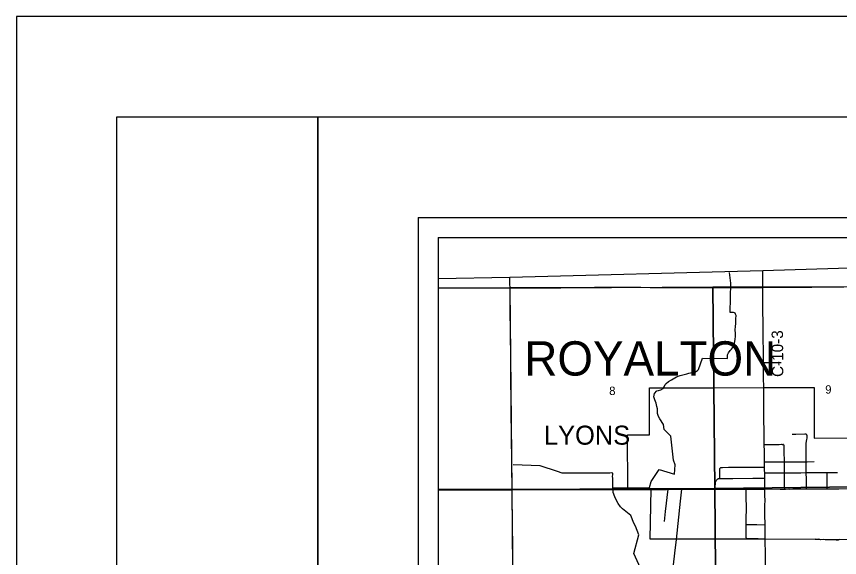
# Model space of a CAD drawing. Extents: x 0 to 34, y 0 to 22.
# Drawn here: x 0 to 4.098, y 19.309 to 22 of the extents above; entities that cross this region are included whole.
import ezdxf

# ---------------------------------------------------------------- set-up
doc = ezdxf.new("R2010")
doc.units = 0
for name, color, linetype in [('Default', 7, 'Continuous'), ('GM_X_City_Street', 7, 'Continuous'), ('GM_X_Corporation', 7, 'Continuous'), ('GM_X_Corporation_Text', 7, 'Continuous'), ('GM_X_County_Road', 7, 'Continuous'), ('GM_X_County_Road_Text', 7, 'Continuous'), ('GM_X_Minor_River', 7, 'Continuous'), ('GM_X_Rail_Line', 7, 'Continuous'), ('GM_X_Section', 7, 'Continuous'), ('GM_X_Section_Text', 7, 'Continuous'), ('GM_X_State_Route', 7, 'Continuous'), ('GM_X_Township_Road', 7, 'Continuous'), ('GM_X_Township_Text', 7, 'Continuous'), ('SH_Border', 7, 'Continuous'), ('SH_Cut_Line', 7, 'Continuous'), ('SH_Data', 7, 'Continuous')]:
    doc.layers.add(name, color=color, linetype=linetype)

msp = doc.modelspace()

# ---------------------------------------------------------------- linework, layer by layer
at = {"layer": 'Default'}
msp.add_lwpolyline([(4.4698, 20.7584), (3.7151, 20.7343), (2.4566, 20.7022), (2.1, 20.6957), (2.1, 16.6348)], dxfattribs=at)
for points in [[(2.1, 20.648), (2.1, 19.6466), (2.4678, 19.6478), (2.4571, 20.6489)], [(2.1, 19.6466), (2.1, 18.6532), (2.4755, 18.6539), (2.4678, 19.6478)]]:
    msp.add_lwpolyline(points, close=True, dxfattribs=at)
at = {"layer": 'GM_X_City_Street'}
for points in [[(3.9318, 19.8282), (3.9317, 19.8653), (3.9316, 19.8725), (3.9316, 19.8756), (3.9319, 19.8806), (3.9323, 19.8841), (3.9336, 19.8901), (3.9345, 19.8944), (3.935, 19.8964), (3.9361, 19.9031), (3.9364, 19.9051), (3.9367, 19.907), (3.9368, 19.9096), (3.9368, 19.9116), (3.9367, 19.9136), (3.9361, 19.9161), (3.9354, 19.9182), (3.9342, 19.9198), (3.9335, 19.9206), (3.9328, 19.9212), (3.9321, 19.9215), (3.9312, 19.9219), (3.9299, 19.9222), (3.9281, 19.9225), (3.9251, 19.9225), (3.8793, 19.9215), (3.8612, 19.9209)], [(3.7229, 19.8714), (3.7584, 19.8713), (3.7963, 19.8717), (3.8089, 19.8719), (3.812, 19.8718), (3.8152, 19.8714)], [(3.8246, 19.6496), (3.8243, 19.6651), (3.8239, 19.6776), (3.8237, 19.7026), (3.8234, 19.7301), (3.8229, 19.785), (3.8223, 19.8379), (3.8223, 19.864), (3.8222, 19.865), (3.8222, 19.8657), (3.8216, 19.867), (3.8207, 19.868), (3.8194, 19.8692), (3.8186, 19.8699), (3.8178, 19.8704), (3.817, 19.8709), (3.8163, 19.8711), (3.8152, 19.8714)], [(3.9331, 19.6501), (3.9324, 19.6643), (3.9326, 19.6969), (3.9322, 19.7311), (3.9321, 19.7439), (3.9319, 19.7731), (3.9316, 19.7853), (3.9318, 19.8282)], [(3.5014, 19.7018), (3.5014, 19.7174), (3.5015, 19.7331), (3.5014, 19.7456), (3.5015, 19.7472), (3.5017, 19.7487), (3.502, 19.7501), (3.5024, 19.7515), (3.5029, 19.7527), (3.5038, 19.754), (3.5046, 19.755), (3.5061, 19.7561)], [(3.5061, 19.7561), (3.5079, 19.7567), (3.5094, 19.757), (3.5112, 19.757), (3.5143, 19.7572), (3.5451, 19.7575), (3.659, 19.7578), (3.7084, 19.758), (3.7243, 19.758)], [(3.7239, 19.7848), (3.7673, 19.7848), (3.8229, 19.785), (3.825, 19.785), (3.8797, 19.7852), (3.9316, 19.7853), (3.9362, 19.7852), (3.9716, 19.7863)], [(3.7249, 19.7306), (3.744, 19.7303), (3.7497, 19.73), (3.7618, 19.7303), (3.8234, 19.7301), (3.861, 19.7299), (3.9046, 19.7303), (3.9322, 19.7311), (3.954, 19.7314), (3.9913, 19.7319), (4.0131, 19.7321), (4.0355, 19.7322), (4.0691, 19.7322), (4.0878, 19.7325)], [(4.0366, 19.6505), (4.0362, 19.6729), (4.0358, 19.7009), (4.0355, 19.7322)], [(3.4796, 19.6491), (3.4789, 19.6605), (3.4798, 19.6776), (3.4803, 19.6824), (3.4808, 19.6839), (3.4819, 19.6876), (3.4837, 19.6913), (3.4854, 19.6938), (3.4876, 19.6963), (3.4896, 19.6984), (3.4912, 19.6997), (3.4928, 19.7006), (3.4943, 19.7011), (3.4977, 19.7016), (3.5014, 19.7018)], [(3.5014, 19.7018), (3.5215, 19.7021), (3.5551, 19.7023), (3.567, 19.7026), (3.6655, 19.703), (3.7118, 19.7032), (3.7256, 19.7032)], [(3.2268, 19.488), (3.2318, 19.5371), (3.244, 19.6495)], [(3.634, 19.4055), (3.6336, 19.4064), (3.6334, 19.4074), (3.6333, 19.4082), (3.6333, 19.4088), (3.6331, 19.413), (3.6329, 19.422), (3.6327, 19.4441), (3.6324, 19.4689), (3.6325, 19.4725), (3.6324, 19.4936), (3.6337, 19.5617), (3.6334, 19.605), (3.6328, 19.6494)], [(3.6325, 19.4725), (3.6444, 19.4728), (3.6539, 19.4725), (3.6852, 19.4726), (3.727, 19.4721)], [(3.634, 19.4055), (3.6344, 19.4049), (3.635, 19.4045), (3.6358, 19.404), (3.6367, 19.4036), (3.6377, 19.4033), (3.6388, 19.4031), (3.6407, 19.403), (3.6431, 19.4029), (3.6556, 19.4027), (3.6932, 19.4028), (3.7183, 19.4024), (3.7276, 19.4023)]]:
    msp.add_lwpolyline(points, dxfattribs=at)
at = {"layer": 'GM_X_Corporation'}
msp.add_lwpolyline([(3.155, 19.3995), (3.1598, 19.65), (3.0434, 19.6498), (3.0413, 19.9196), (3.1522, 19.9187), (3.151, 20.1523), (3.4671, 20.153), (3.72, 20.1538), (3.9709, 20.1548), (3.9717, 19.9024), (4.2217, 19.9047), (4.2244, 19.6529), (4.2237, 19.397), (3.7274, 19.3997), (3.2857, 19.3997)], close=True, dxfattribs=at)
at = {"layer": 'GM_X_County_Road'}
for p, q in [((3.7243, 19.758), (3.7239, 19.7848)), ((3.7256, 19.7032), (3.7249, 19.7306)), ((3.7258, 19.6283), (3.7258, 19.6501)), ((3.7276, 19.4023), (3.727, 19.4721))]:
    msp.add_line(p, q, dxfattribs=at)
for points in [[(3.7161, 20.6524), (3.716, 20.6583), (3.7157, 20.7081), (3.7153, 20.7337)], [(2.4571, 20.6512), (2.457, 20.6688), (2.4568, 20.7016)], [(3.7192, 20.2789), (3.7191, 20.297), (3.7186, 20.3437), (3.7179, 20.3904), (3.7165, 20.624), (3.7161, 20.6524)], [(2.4675, 19.6482), (2.467, 19.6958), (2.4669, 19.7145), (2.4665, 19.7549), (2.4643, 19.9414), (2.4632, 20.0097), (2.4627, 20.0781), (2.4613, 20.2055), (2.4606, 20.2459), (2.4606, 20.2739), (2.4587, 20.4542), (2.4582, 20.5164), (2.4576, 20.5879), (2.4571, 20.6512)], [(3.7202, 20.1532), (3.7196, 20.2053), (3.7192, 20.2789)], [(3.7229, 19.8714), (3.7209, 20.0624), (3.7204, 20.1058), (3.7202, 20.1532)], [(3.7239, 19.7848), (3.7238, 19.7993), (3.7233, 19.8366), (3.7229, 19.8714)], [(3.7249, 19.7306), (3.7244, 19.7413), (3.7244, 19.7501), (3.7243, 19.758)], [(3.7258, 19.6501), (3.7259, 19.6669), (3.7256, 19.6916), (3.7256, 19.7032)], [(2.4799, 18.3001), (2.4798, 18.3093), (2.4781, 18.4678), (2.4758, 18.6792), (2.4742, 18.8657), (2.4737, 18.9435), (2.4734, 18.9652), (2.4731, 18.9994), (2.4722, 19.0771), (2.4716, 19.1517), (2.4708, 19.2792), (2.4703, 19.3538), (2.4679, 19.6057), (2.4675, 19.6482)], [(3.7262, 19.5673), (3.7263, 19.5766), (3.7265, 19.5858), (3.7258, 19.6233), (3.7258, 19.6283)], [(3.727, 19.4721), (3.7264, 19.5235), (3.7261, 19.5641), (3.7262, 19.5673)], [(3.7277, 19.3981), (3.7277, 19.3991), (3.7276, 19.4023)], [(3.735, 18.6489), (3.7343, 18.6815), (3.7335, 18.7902), (3.7331, 18.8181), (3.7327, 18.8647), (3.7322, 18.9113), (3.7306, 19.0916), (3.73, 19.1751), (3.7291, 19.2526), (3.7285, 19.3334), (3.728, 19.3863), (3.7277, 19.3981)]]:
    msp.add_lwpolyline(points, dxfattribs=at)
at = {"layer": 'GM_X_Minor_River'}
for points in [[(2.9689, 19.656), (3.1517, 19.6572), (3.16, 19.6867), (3.2001, 19.7459), (3.2756, 19.7235), (3.2796, 19.7702), (3.2711, 19.7923), (3.2569, 19.9131), (3.2246, 19.9456), (3.2211, 19.9707), (3.2025, 19.9994), (3.1961, 20.0097), (3.1906, 20.0257), (3.1911, 20.0336), (3.1916, 20.042), (3.1912, 20.048), (3.1887, 20.0598), (3.1851, 20.0766), (3.1777, 20.0926), (3.173, 20.1074), (3.1758, 20.1245), (3.1885, 20.1384), (3.1957, 20.1402), (3.2071, 20.1427), (3.2193, 20.1491), (3.2243, 20.1574), (3.2301, 20.1695), (3.2351, 20.1747), (3.2462, 20.1841), (3.2615, 20.1923), (3.2859, 20.2072), (3.3049, 20.2139), (3.3373, 20.2227), (3.3479, 20.2252), (3.3646, 20.2288), (3.3798, 20.2329), (3.3898, 20.2392), (3.3951, 20.2449), (3.4155, 20.3004), (3.5402, 20.2996), (3.5396, 20.3171), (3.5451, 20.3276), (3.5531, 20.3378), (3.56, 20.3457), (3.5689, 20.3581), (3.5751, 20.3729), (3.5784, 20.3948), (3.5797, 20.4081), (3.5791, 20.4229), (3.5785, 20.4408), (3.5795, 20.4574), (3.5812, 20.4722), (3.5821, 20.4863), (3.5818, 20.4969), (3.5824, 20.5132), (3.5802, 20.5193), (3.5772, 20.5246), (3.5742, 20.5262), (3.5689, 20.5281), (3.5537, 20.5279), (3.5557, 20.6732), (3.5495, 20.7261)], [(3.1227, 19.2188), (3.0735, 19.329), (3.0983, 19.4209), (3.0817, 19.4647), (3.0739, 19.48), (3.0588, 19.5181), (3.0171, 19.5511), (3.007, 19.5615), (2.995, 19.5779), (2.9876, 19.592), (2.9787, 19.6115), (2.9713, 19.6324), (2.9689, 19.6545), (2.9691, 19.7011), (2.9677, 19.714), (2.9685, 19.7209), (2.9682, 19.7277), (2.9644, 19.7304), (2.9538, 19.729), (2.7169, 19.729), (2.6931, 19.7372), (2.6077, 19.7647), (2.4728, 19.7694)], [(4.0997, 19.399), (4.0902, 19.3956), (4.0804, 19.3957), (4.069, 19.3962), (4.0576, 19.3967), (4.0474, 19.3976), (4.0371, 19.3965), (4.0258, 19.3963), (4.0159, 19.3979), (4.0045, 19.3968), (3.994, 19.3996), (3.983, 19.399), (3.9758, 19.4009)]]:
    msp.add_lwpolyline(points, dxfattribs=at)
at = {"layer": 'GM_X_Rail_Line'}
msp.add_lwpolyline([(2.1, 19.6449), (2.4687, 19.6463), (3.2362, 19.6474), (3.7244, 19.6491), (5.0197, 19.6574), (5.4852, 19.6574), (5.5146, 19.6675), (5.5588, 19.7034), (6.1514, 20.0969), (6.291, 20.193), (6.3333, 20.2132), (6.3747, 20.2169), (6.4833, 20.2279), (7.4795, 20.3149), (8.1518, 20.3773), (8.7379, 20.4271), (8.9, 20.4441)], dxfattribs=at)
at = {"layer": 'GM_X_Section'}
for points in [[(2.4571, 20.6489), (3.4668, 20.6546), (3.4763, 19.6515), (2.4678, 19.6478)], [(3.4668, 20.6546), (4.4712, 20.6576), (4.4763, 19.663), (3.4763, 19.6515)], [(2.4678, 19.6478), (3.4763, 19.6515), (3.4848, 18.6515), (2.4755, 18.6539)], [(3.4763, 19.6515), (4.4763, 19.663), (4.4846, 18.6535), (3.4848, 18.6515)]]:
    msp.add_lwpolyline(points, close=True, dxfattribs=at)
at = {"layer": 'GM_X_State_Route'}
for points in [[(2.1, 19.6467), (2.1864, 19.647), (2.2953, 19.6478), (2.401, 19.6481), (2.4524, 19.6482)], [(2.4524, 19.6482), (2.4675, 19.6482), (2.5099, 19.6483), (2.569, 19.6485), (2.6312, 19.6486), (2.7338, 19.6489), (2.7867, 19.649), (2.9049, 19.649), (2.9391, 19.6491), (2.992, 19.6493), (3.0426, 19.6492)], [(3.0426, 19.6492), (3.0436, 19.6492), (3.1039, 19.6492), (3.16, 19.6494)], [(3.16, 19.6494), (3.244, 19.6495), (3.2777, 19.6495), (3.3123, 19.6496), (3.3243, 19.6496), (3.4197, 19.6492), (3.4796, 19.6491), (3.5127, 19.6492), (3.581, 19.6493), (3.5989, 19.6494)], [(3.5989, 19.6494), (3.6328, 19.6494), (3.6679, 19.6494), (3.6689, 19.6494)], [(3.6689, 19.6494), (3.7258, 19.6501), (3.7586, 19.6498)], [(3.7586, 19.6498), (3.8013, 19.6495), (3.8246, 19.6496), (3.8287, 19.6496)], [(3.8287, 19.6496), (3.8448, 19.6497), (3.848, 19.6495), (3.8655, 19.6501), (3.9278, 19.65), (3.9331, 19.6501), (3.9808, 19.6505), (4.0053, 19.6504), (4.0235, 19.6504), (4.0263, 19.6503), (4.0295, 19.6505), (4.0354, 19.6505), (4.0366, 19.6505), (4.0945, 19.651), (4.1506, 19.6514), (4.2004, 19.6522), (4.2246, 19.6523)]]:
    msp.add_lwpolyline(points, dxfattribs=at)
at = {"layer": 'GM_X_Township_Road'}
msp.add_line((3.7192, 20.2789), (3.8066, 20.2792), dxfattribs=at)
for points in [[(2.4571, 20.6512), (2.4893, 20.6514), (2.6571, 20.6521), (2.7504, 20.6526), (2.8778, 20.6531), (2.9959, 20.6535), (3.1078, 20.6532), (3.1544, 20.6526), (3.2631, 20.6523), (3.288, 20.6521), (3.3595, 20.6522), (3.4682, 20.6518), (3.5055, 20.652), (3.6174, 20.6523), (3.7044, 20.6524), (3.7161, 20.6524)], [(3.7161, 20.6524), (3.8419, 20.6538), (3.9601, 20.6544), (4.0192, 20.655), (4.0534, 20.6552), (4.1187, 20.6558), (4.2494, 20.6561), (4.4048, 20.6565), (4.4698, 20.657)], [(2.1, 20.6497), (2.1164, 20.6498), (2.2096, 20.6501), (2.3402, 20.6505), (2.4241, 20.651), (2.4571, 20.6512)], [(3.2859, 19.3991), (3.3064, 19.5891), (3.3123, 19.6496)], [(3.2322, 18.6489), (3.2319, 18.7206), (3.2316, 18.814), (3.2308, 18.8762), (3.2311, 18.8949), (3.2319, 18.9105), (3.2345, 18.9384), (3.2404, 18.9941), (3.2446, 19.0374), (3.2521, 19.1054), (3.2615, 19.1858), (3.2666, 19.229), (3.2784, 19.331), (3.2859, 19.3991)]]:
    msp.add_lwpolyline(points, dxfattribs=at)
at = {"layer": 'SH_Border'}
for points in [[(0.5, 21.5), (1.5, 21.5), (1.5, 0.5), (0.5, 0.5)], [(1.5, 21.5), (33.5, 21.5), (33.5, 0.5), (1.5, 0.5)]]:
    msp.add_lwpolyline(points, close=True, dxfattribs=at)
at = {"layer": 'SH_Cut_Line'}
for points in [[(0, 0), (34, 0), (34, 22), (0, 22)], [(2.1, 20.6957), (2.1, 14.1), (8.9, 14.1), (8.9, 20.8277), (8.6079, 20.8216), (7.476, 20.811), (6.4789, 20.8005), (5.4741, 20.7803), (4.4698, 20.7584), (3.7151, 20.7343), (2.4566, 20.7022)]]:
    msp.add_lwpolyline(points, close=True, dxfattribs=at)
at = {"layer": 'SH_Data'}
for p, q in [((2, 21), (9, 21)), ((2, 21), (2, 14)), ((2.1, 20.9), (2.1, 14.1)), ((2.1, 20.9), (8.9, 20.9))]:
    msp.add_line(p, q, dxfattribs=at)

# ---------------------------------------------------------------- texts
at = {"layer": 'GM_X_Corporation_Text'}
msp.add_text('LYONS', height=0.0947, rotation=0, dxfattribs=at).set_placement((2.626, 19.8701))
at = {"layer": 'GM_X_County_Road_Text'}
msp.add_text('C-10-3', height=0.05682, rotation=90.4801, dxfattribs=at).set_placement((3.8179, 20.2071))
at = {"layer": 'GM_X_Section_Text'}
for s, p in [('9', (4.0263, 20.1238)), ('8', (2.9509, 20.1171))]:
    msp.add_text(s, height=0.0419, rotation=0, dxfattribs=at).set_placement(p)
at = {"layer": 'GM_X_Township_Text'}
msp.add_text('ROYALTON', height=0.17045, rotation=0, dxfattribs=at).set_placement((2.5283, 20.2139))

doc.saveas('drawing.dxf')
